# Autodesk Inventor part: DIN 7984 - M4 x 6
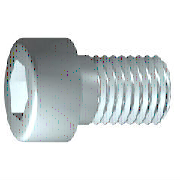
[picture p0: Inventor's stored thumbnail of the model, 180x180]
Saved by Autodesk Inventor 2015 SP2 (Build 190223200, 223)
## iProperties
IsCustomPart: 0
Created: 2012-02
Part Number: DIN 7984 - M4 x 6
Material: Stahl, weich
Description: Zylinderkopfschraube
Document SubType Name: Modeling
Standard: DIN 7984
Designer: rYan
Standard Revision: 1985
Standards Organization: DIN
Language: de-DE
Size Designation: M4 x 6
Categories: <MemberInstance><Categories><Category DisplayName="Verbindungselemente" InternalName="e4da775c-781d-43d5-af7c-5136215cf5a6" Mnemonic="FSTN"><Category DisplayNam
Density: 7.85 g/cm^3
Mass: 1.31215 g
Surface Area: 2.27551 cm^2
Volume: 0.167153 cm^3
Appearance: Halbpoliert
Author: rYan
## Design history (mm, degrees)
sketch "Skizze1"
  geometry: L1 (0.333, 0)-(6, 0); L2 (6, 0)-(6, 2); L3 (6, 2)-(2.1, 2); L4 (2.1, 2)-(1.67, 2); L5 (1.67, 2)-(0, 2); L6 (0, 2)-(0, 3.5); L7 (0, 3.5)-(-2.8, 3.5); L8 (-2.8, 3.5)-(-2.8, 1.443); L9 (-2.8, 1.443)-(-0.5, 1.443); L10 (-0.5, 1.443)-(0.333, 0); L11 (-4.56, 0)-(7.76, 0) reference; L12 (0, -0.7)-(0, 4.2) reference; L13 (2.1, 2)-(0, 2)
  constraints: 22 end point, 6 parallel, 2 collinear, 2 perpendicular, 1 horizontal, 1 point on line
  dimensions: "d1" = 3.9 distance from line of L3.end L2 (= GEL); "d2" = 0.42952 distance of L4.end L3.end (computed from GAL); "d3" = 2.8 distance between parallel lines of L8 L6 (= KOH); "d4" = 2.3 distance of L8.end L9.end (= INTI); "d5" = 60 deg angle of L10 L1; "d6" = 4 diameter of L3 L1 (= GD); "d7" = 4 diameter of L5 L1 (= BDM); "d8" = 2.88675 diameter of L9 L1 (= 1.1547 x SW); "d9" = 7 diameter of L7 L1 (= KOD); "d26" = 6 distance between parallel lines of L12 L2 (= NLG)
revolve "Körper" sketch "Skizze1" stored, may be unused: angle "d10" = 90 deg
sketch "Skizze2"
  geometry: L1 (0, -4.9)-(0, 4.9) reference; L2 (-4.9, 0)-(4.9, 0) reference; L3 (1.443, 0)-(0.722, -1.25); L4 (0.722, -1.25)-(-0.722, -1.25); L5 (-0.722, -1.25)-(-1.443, 0); L6 (-1.443, 0)-(-0.722, 1.25); L7 (-0.722, 1.25)-(0.722, 1.25); L8 (0.722, 1.25)-(1.443, 0); 2 further points
  constraints: 12 end point, 1 coincident, 1 horizontal alignment, 1 point on line, 12 other
extrude "Loch" join sketch "Skizze2" stored distance "d11" = 10; taper "d12" = 0 deg
workplane "Work Plane1"
fillet "Fillet2" dims "d30" = 0.1 (= R)
body "Solid1"
fillet "Rundung1" dims "d17" = 0.4 (= RR)
feature "Gewinde" dims "d13" = 3.9 (= GEL), "d14" = 0
chamfer "Fase1" distance "d15" = 0.42941 (= -0.5 x SPD + 0.5 x GD); stored, may be unused: second distance "d16" = 0.42941 (= GUL), angle "d27" = 45 deg
other parameters: "GD" = 4 (= NND) [user parameter; used in 2 equation terms], "NLG" = 6 [user parameter; used in 1 equation term], "GEL" = 3.9 [user parameter; used in 2 equation terms], "KOD" = 7 [user parameter; used in 1 equation term], "KOH" = 2.8 [user parameter; used in 1 equation term], "INTI" = 2.3 [user parameter; used in 1 equation term], "GAL" = 0.42941 (= 0.61345 x PTC) [user parameter; used in 1 equation term], "GUL" = 0.42941 (= 0.61345 x PTC) [user parameter; used in 1 equation term], "BDM" = 4 (= NND) [user parameter; used in 1 equation term], "SW" = 2.5 [user parameter; used in 2 equation terms], "RR" = 0.4 [user parameter; used in 1 equation term], "SPD" = 3.14117 (= NND - 1.2269 x PTC) [user parameter; used in 1 equation term], "d19" = 0, "d28" = 0, "d29" = 0, "R" = 0.1 [user parameter; used in 1 equation term], "TOA" = 30 deg [user parameter], "GD1" = 3.14117 (= THREADDIA - 1.2269 x PTC) [user parameter], "THREADDIA" = 4 [user parameter; used in 1 equation term], "FAWI" = 45 deg [user parameter], "ANG" = 120 deg [user parameter], "TPU" = 14.28571 (computed from PTC) [user parameter], "PTC" = 0.7 [user parameter; used in 5 equation terms], "NND" = 4 [user parameter; used in 3 equation terms], "E0" = 2.8875 (= 1.155 x SW) [user parameter]
